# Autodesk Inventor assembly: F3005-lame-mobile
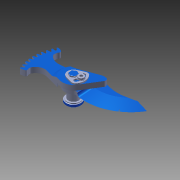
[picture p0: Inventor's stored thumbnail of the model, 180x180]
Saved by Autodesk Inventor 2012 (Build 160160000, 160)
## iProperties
Created: 2014-12
Part Number: F3005-lame-mobile
Document SubType Name: Assembly
Designer: Bruno
Mass: 16.4394 g
Surface Area: 115.66 cm^2
Volume: 16.4394 cm^3
Density: 1 g/cm^3
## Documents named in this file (8)
- F:\Systèmes\secateur-hydrogene-Pragma\Documentation\Dossier technique Infaco F3005\Solidworks\Composants importés\F3005-lame-mobile.iam
- F:\Systèmes\secateur-hydrogene-Pragma\Documentation\Dossier technique Infaco F3005\Solidworks\Composants importés\F3005\Coussinet lame_Cote mini.ipt
- F:\Systèmes\secateur-hydrogene-Pragma\Documentation\Dossier technique Infaco F3005\Solidworks\Composants importés\F3005\Axe lame_cote maxi.ipt
- F:\Systèmes\secateur-hydrogene-Pragma\Documentation\Dossier technique Infaco F3005\Solidworks\Composants importés\F3005\Lamelle blocage.ipt
- F:\Systèmes\secateur-hydrogene-Pragma\Documentation\Dossier technique Infaco F3005\Solidworks\Composants importés\F3005\Vis M4X8.ipt
- F:\Systèmes\secateur-hydrogene-Pragma\Documentation\Dossier technique Infaco F3005\Solidworks\Composants importés\F3005\Rondelles M4.ipt
- F:\Systèmes\secateur-hydrogene-Pragma\Documentation\Dossier technique Infaco F3005\Solidworks\Composants importés\F3005\Crémaillère_Taillage.ipt
- F:\Systèmes\secateur-hydrogene-Pragma\Documentation\Dossier technique Infaco F3005\Solidworks\Composants importés\F3005\Lame_cote mini.ipt
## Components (7 placed, 7 different names)
1. Coussinet lame_Cote mini:1
2. Axe lame_cote maxi:1
3. Lamelle blocage:1
4. Vis M4X8:1
5. Rondelles M4:1
6. Crémaillère_Taillage:1
7. Lame_cote mini:1
